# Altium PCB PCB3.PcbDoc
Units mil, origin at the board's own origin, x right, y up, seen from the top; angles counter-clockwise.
Board outline 1968.5 x 1968.5 mil, 4 copper layers (Top Layer, Internal Plane 1, Internal Plane 2, Bottom Layer), stack 18.2 mil thick; 11 components, 12 nets, 36 pads, 0 vias.
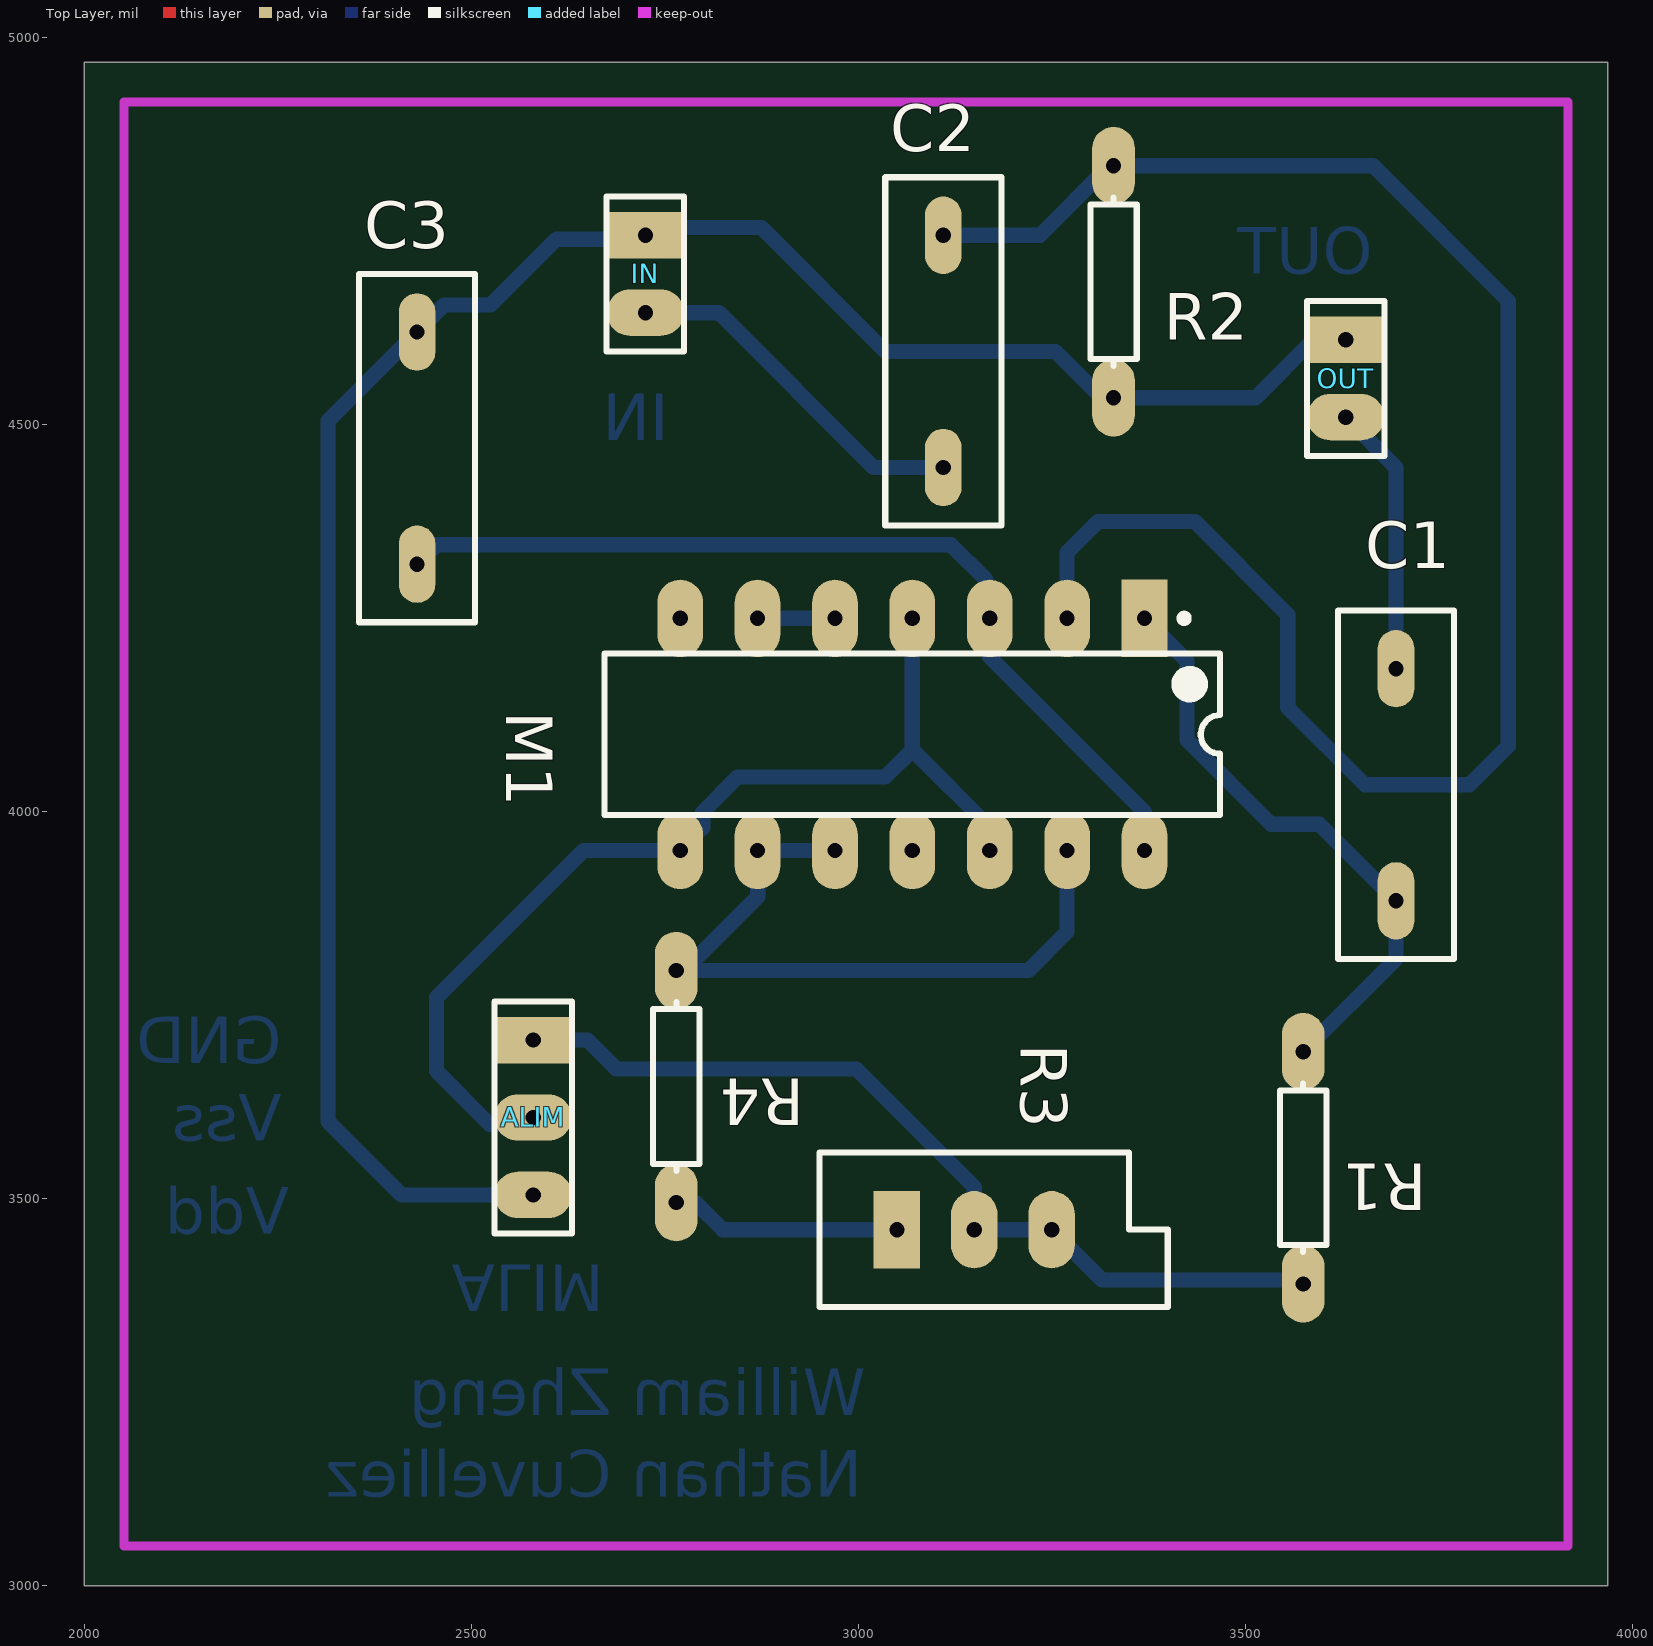
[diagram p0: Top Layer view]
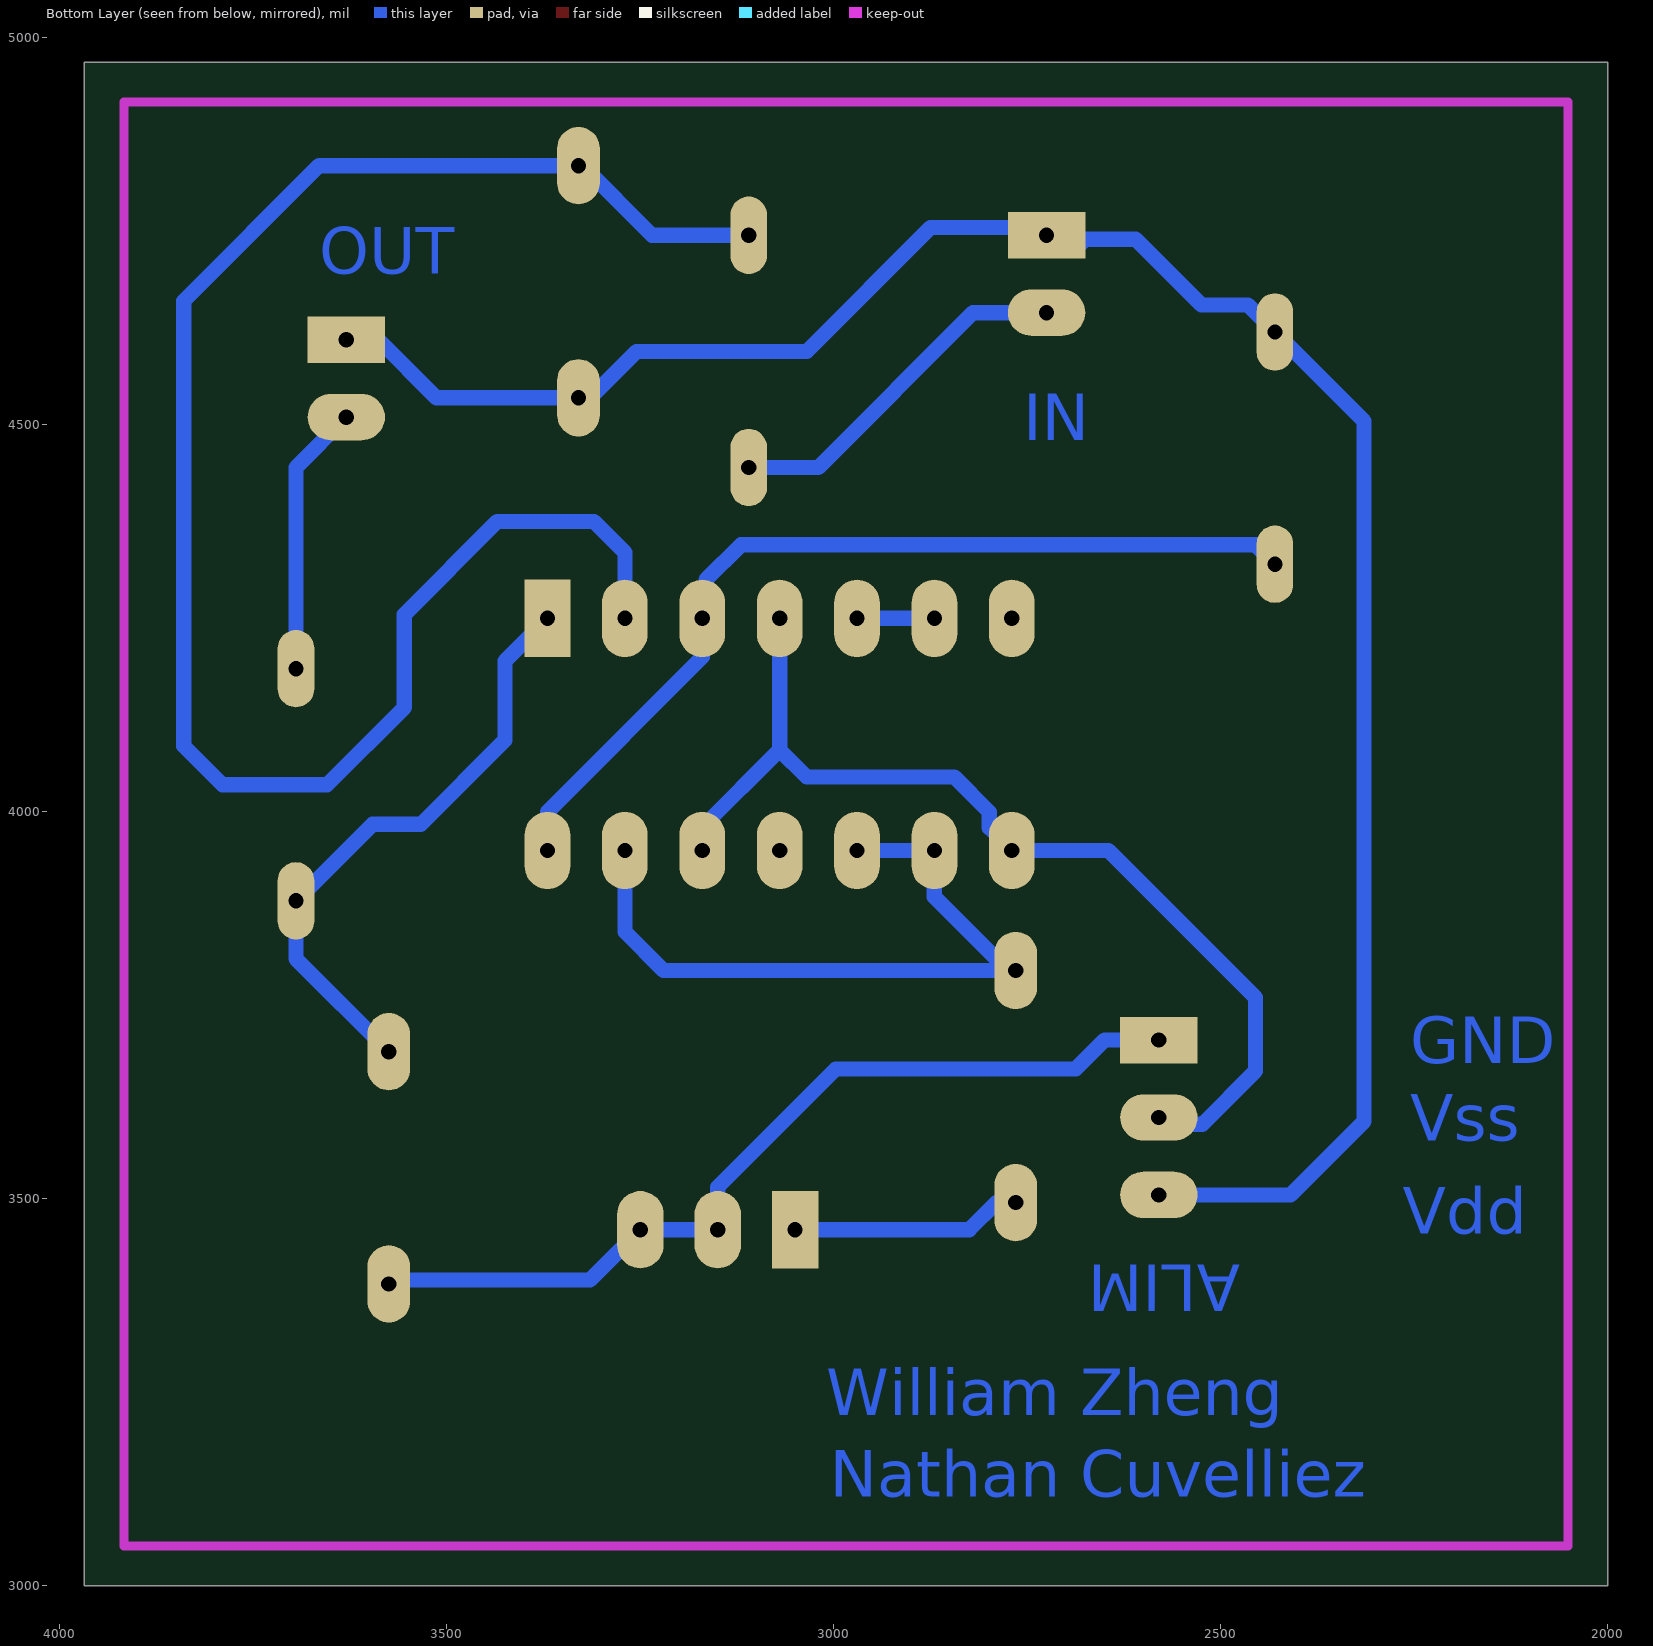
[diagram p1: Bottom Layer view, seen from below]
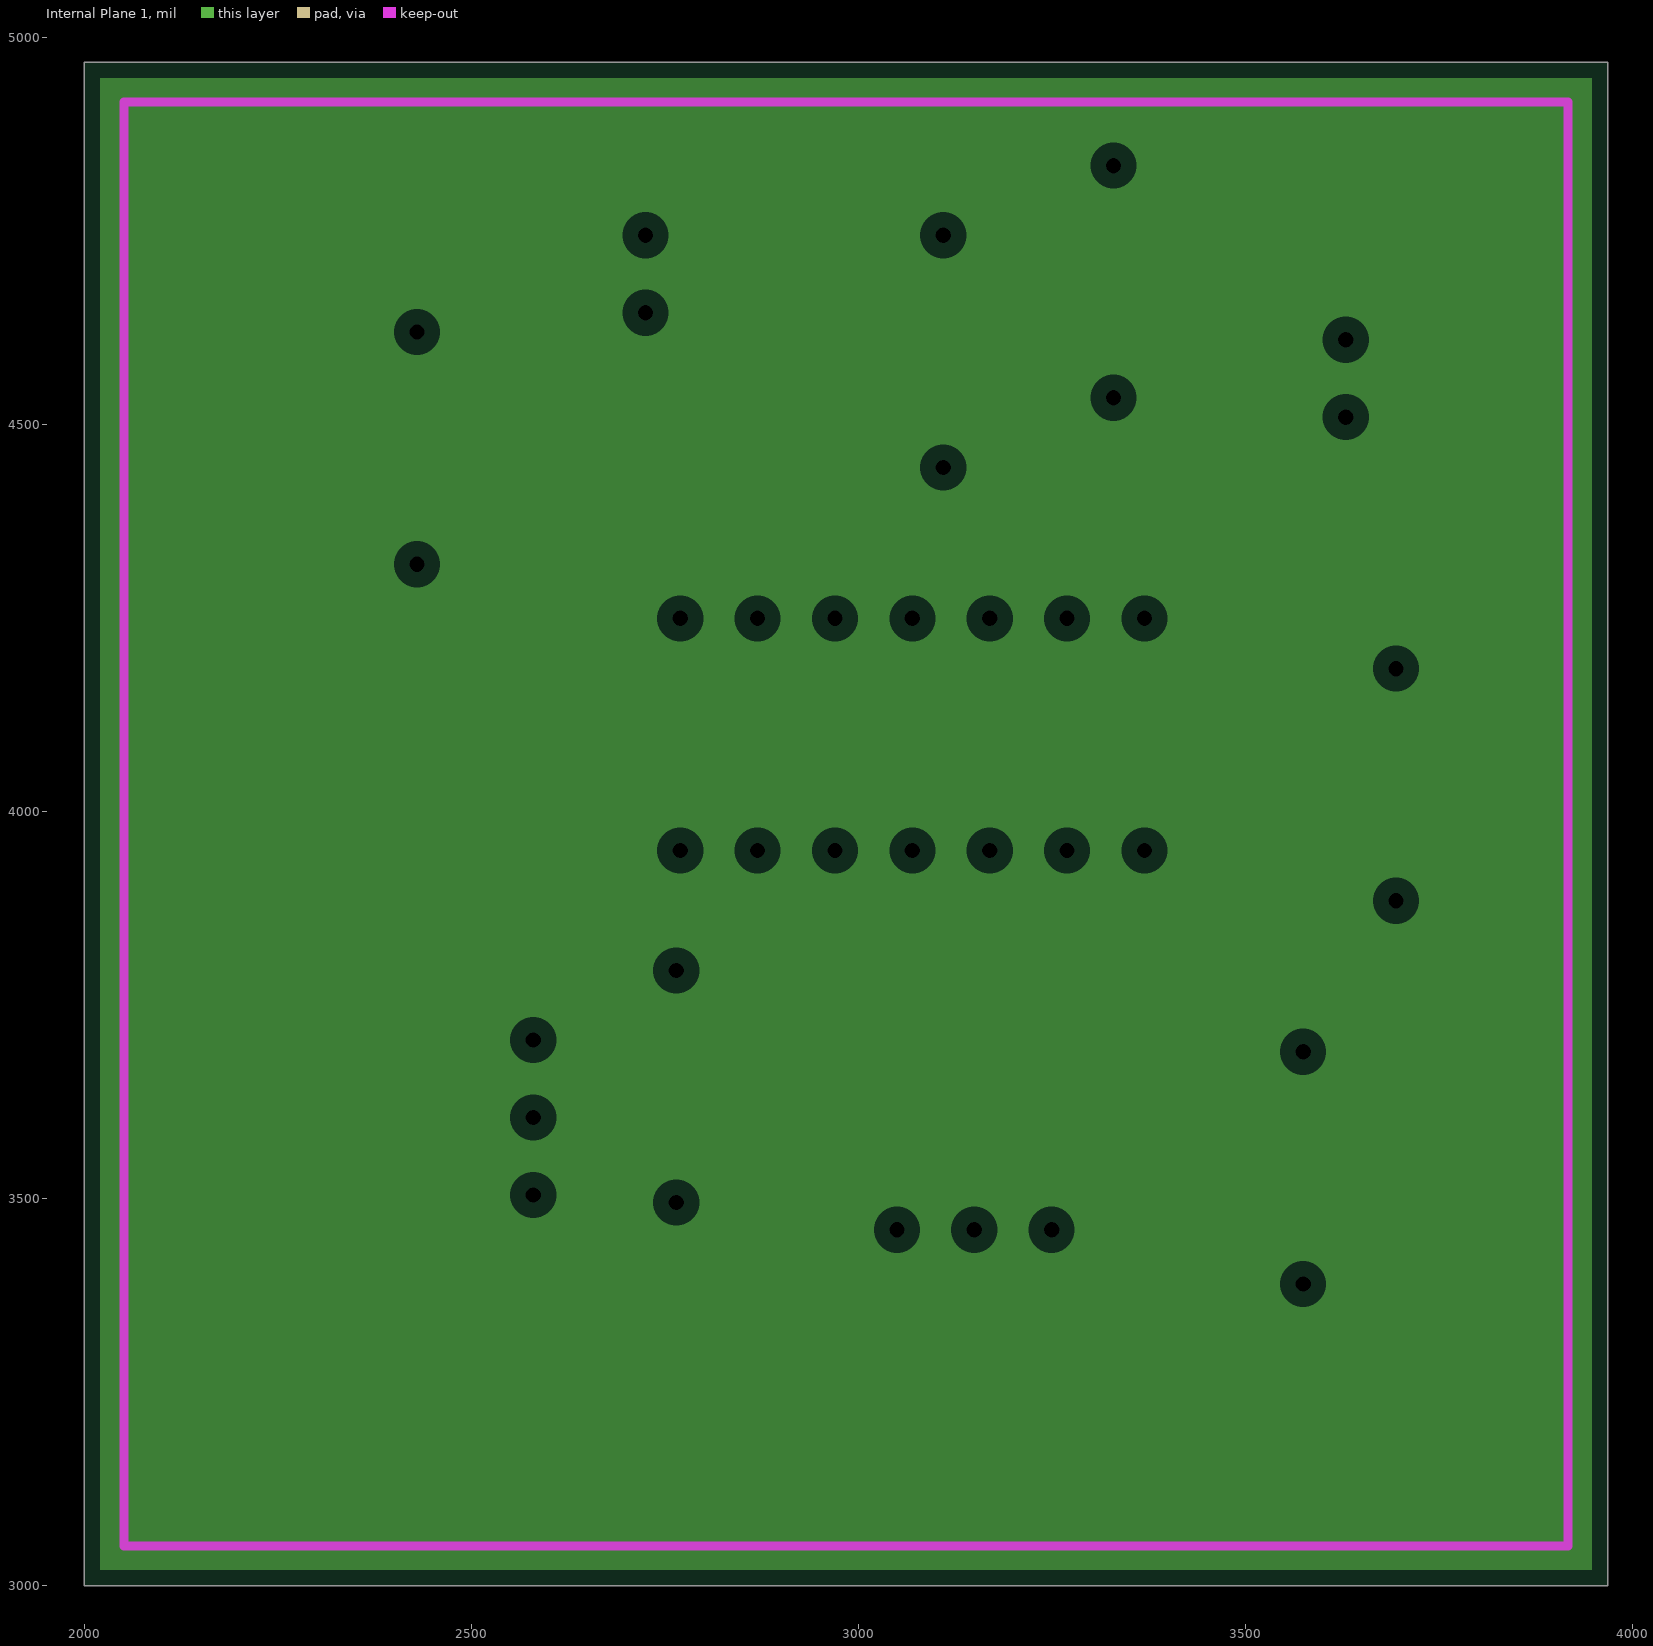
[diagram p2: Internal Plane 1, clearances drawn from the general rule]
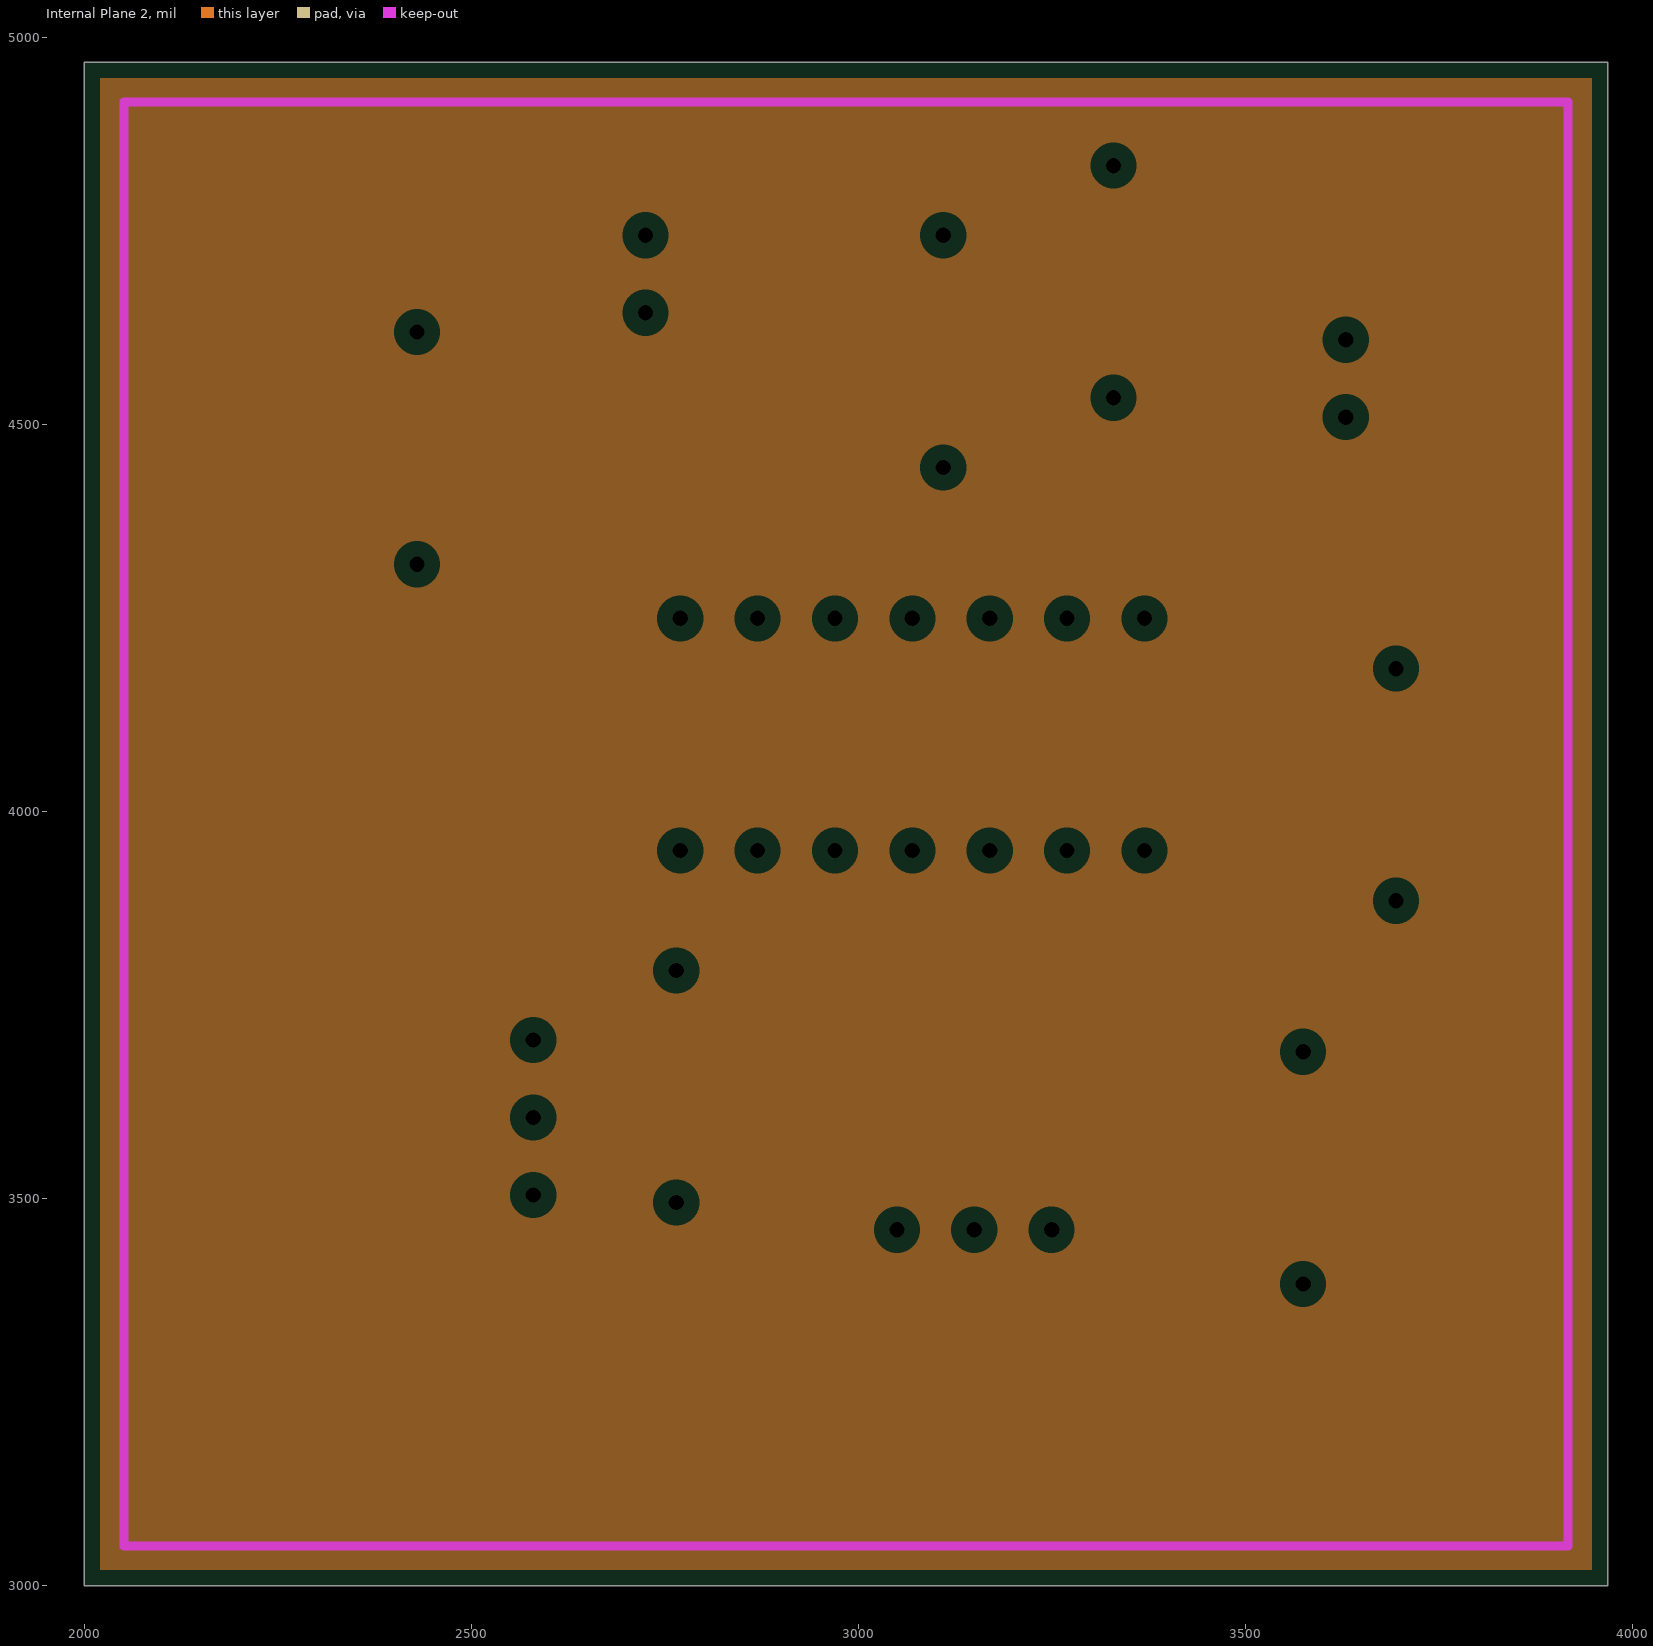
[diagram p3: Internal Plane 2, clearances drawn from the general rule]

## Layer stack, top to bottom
Top Solder: solder mask 0.4, Solder Resist, Dk 3.5
Top Layer: signal copper 1.4
Internal Plane 1: plane copper 1.4
Internal Plane 2: plane copper 1.4
Dielectric 1: dielectric 12.6, FR-4, Dk 4.8
Bottom Layer: signal copper 1.4
Bottom Solder: solder mask 0.4, Solder Resist, Dk 3.5

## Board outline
2000,3000 3968.5,3000 3968.5,4968.5 2000,4968.5

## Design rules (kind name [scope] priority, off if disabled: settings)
Clearance [All] p1: gap=31.5
PlaneClearance [All] p1: clearance=20
PlaneConnect [All] p1: planeconnectstyle=Relief reliefexpansion=20 reliefentries=4 reliefconductorwidth=10 reliefairgap=10
PolygonConnect [All] p1: connectstyle=Relief reliefconductorwidth=10 reliefentries=4 polygonreliefangle="90 Angle" airgapwidth=10
RoutingVias [All] p1: holewidth=31.5 width=62.99 viastyle="Through Hole" minholewidth=28 minwidth=50 maxholewidth=28 maxwidth=50
SolderMaskExpansion [All] p1: expansion=4
Width [All] p1: maxlimit=19.68 minlimit=19.68 preferedwidth=19.68
28 further rules are at their usual default settings.

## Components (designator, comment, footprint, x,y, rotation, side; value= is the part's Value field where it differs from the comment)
ALIM "Header 3" HDR1X3 2580,3705 r270 top
C1 "Cap" RAD-0.3 3695,4035 r90 top
C2 "Cap" RAD-0.3 3110,4595 r90 top
C3 "Cap" RAD-0.3 2430,4470 r90 top
IN "IN" HDR1X2 2725,4745 r270 top
M1 "ALD1106" DIP-14 3070,4100 r270 top
OUT "OUT" HDR1X2 3630,4610 r270 top (schematic designator Out)
R1 "Res1" AXIAL-0.3 3575,3540 r270 top
R2 "Res1" AXIAL-0.3 3330,4685 r90 top
R3 "RPot" VR5 3150,3460 r0 top
R4 "Res1" AXIAL-0.3 2765,3645 r270 top

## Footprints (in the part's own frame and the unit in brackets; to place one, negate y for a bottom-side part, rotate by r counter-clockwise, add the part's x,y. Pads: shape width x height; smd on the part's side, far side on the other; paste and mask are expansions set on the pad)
AXIAL-0.3 [mm] "Axial Device, Thru-Hole; 2 Leads; 0.3 in Pin Spacing"
  oval 2.54x1.4 hole 0.5: 1(-3.81,0) 2(3.81,0)
  silkscreen extent -2.77,-0.76 2.77,0.76
DIP-14 [mm] "DIP, 14-Pin, Row Spacing 7.62 mm, Pitch 2.54 mm"
  rect 2.54x1.5 hole 0.5: 1(-3.81,7.62)
  oval 2.54x1.5 hole 0.5: 2(-3.81,5.08) 3(-3.81,2.54) 4(-3.81,0) 5(-3.81,-2.54) 6(-3.81,-5.08) 7(-3.81,-7.62) 8(3.81,-7.62) 9(3.81,-5.08) 10(3.81,-2.54) 11(3.81,0) 12(3.81,2.54) 13(3.81,5.08) 14(3.81,7.62)
  silkscreen extent -3.93,-10.1 2.65,10.1, body extent -3.6,-10.1 3.6,10.1, height 5.08
HDR1X2 [mil] "Connector; Header; 2 Position"
  rect 60x100 hole 19.68: 1(0,0)
  oval 60x100 hole 19.68: 2(100,0)
  silkscreen extent -50,-50 150,50
HDR1X3 [mil] "Connector; Header; 3 Position"
  rect 60x100 hole 19.68: 1(0,0)
  oval 60x100 hole 19.68: 2(100,0) 3(200,0)
  silkscreen extent -50,-50 250,50
RAD-0.3 [mm] "Radial Cap, Thru-Hole; 2 Leads; 0.3 in Pin Spacing"
  oval 2.54x1.2 hole 0.5: 1(-3.81,0) 2(3.81,0)
  silkscreen extent -5.71,-1.91 5.71,1.91
VR5 [mil] "Thru-Hole; 3 Leads"
  rect 60x100 hole 19.68: 1(-100,0)
  oval 60x100 hole 19.68: 2(0,0) 3(100,0)
  silkscreen extent -200,-100 250,100

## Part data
ALIM: "Header, 3-Pin"
C1 C2 C3: "Capacitor"
IN OUT: library part "Header 2", "Header, 2-Pin"
M1: "Quad N-channel matched MOSFET array"
R1 R2 R4: "Resistor"
R3: "Potentiometer"

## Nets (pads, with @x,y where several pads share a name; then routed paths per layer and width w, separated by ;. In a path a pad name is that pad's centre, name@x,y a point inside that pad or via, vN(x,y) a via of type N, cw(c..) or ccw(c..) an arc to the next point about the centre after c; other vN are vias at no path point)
GND: ALIM.3 C3.2 IN.1 OUT.1 R2.1 | length 2663.9
  Bottom Layer w19.68: ALIM.3 2410,3505 2315,3600 2315,4505 C3.2 2465,4655 2525,4655 2610,4740 2675,4740 IN.1@2689.13,4725.87 ; IN.1@2760,4755 2875,4755 3035,4595 3255,4595 R2.1@3315,4535 ; R2.1 3513.27,4535 3588.27,4610 OUT.1
NetALIM_1: ALIM.1 R1.2 R3.2 R3.3 | length 1160.6
  Bottom Layer w19.68: ALIM.1 2650,3705 2687.5,3667.5 2997.5,3667.5 3150,3515 R3.2 R3.3 3315,3395 R1.2@3570,3395 ; R1.2@3565,3390 R1.2
NetALIM_2: ALIM.2 M1.4 M1.8 M1.12 | length 1340.8
  Bottom Layer w19.68: ALIM.2@2571.24,3596.24 2523.76,3596.24 2455,3665 2455,3760 2645,3950 M1.8 2770,3950.22 2799.13,3979.35 2799.13,3999.83 2844.31,4045 3035,4045 3070,4080 ; M1.4 3070,4080 ; M1.12 3170,3980 3070,4080
NetC1_1: C1.1 M1.1 R1.1 | length 780.9
  Bottom Layer w19.68: M1.1 3425,4195 3425,4170 3425,4092.62 3533.8,3983.82 3596.18,3983.82 C1.1 3695,3810 R1.1
NetC1_2: C1.2 OUT.2 | length 351.9
  Bottom Layer w19.68: OUT.2 3695,4445 C1.2
NetC2_1: C2.1 IN.2 | length 467.8
  Bottom Layer w19.68: IN.2 2820,4645 3020,4445 C2.1
NetC2_2: C2.2 M1.2 R2.2 | length 2313.2
  Bottom Layer w19.68: C2.2 3235,4745 R2.2@3325,4835 ; M1.2 3270,4335 3310,4375 3435,4375 3555,4255 3555,4135 3655,4035 3790,4035 3840,4085 3840,4660 3665,4835 R2.2
NetC3_1: C3.1 M1.3 M1.14 | length 1186.6
  Bottom Layer w19.68: C3.1 2455,4345 3120,4345 3165,4300 M1.3@3165,4260 ; M1.3 3170,4200 3370,4000 M1.14@3370,3950.22
NetM1_4: M1.7
NetM1_5: M1.5 M1.6 | length 101.5
  Bottom Layer w19.68: M1.6@2870,4251.51 M1.6 M1.5
NetM1_9: M1.9 M1.10 M1.13 R4.1 | length 935.1
  Bottom Layer w19.68: M1.10 M1.9 2870.06,3890.15 2775.14,3795.02 R4.1 3220,3795 3270,3845 M1.13
NetR3_1: R3.1 R4.2 | length 274.5
  Bottom Layer w19.68: R4.2@2790,3495 2825,3460 R3.1
pads on no net: M1.11

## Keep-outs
Keep-Out Layer:
  lines w11.81: 2051.18,3051.18 3917.32,3051.18 3917.32,4917.32 2051.18,4917.32 2051.18,3051.18

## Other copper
Bottom Layer:
  text "GND" at 2255,3675 h60
  text "Vss" at 2255,3575 h60
  text "Vdd" at 2265,3455 h60
  text "William Zheng" at 3010,3220 h60
  text "Nathan Cuvelliez" at 3005,3115 h60

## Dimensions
2051.18,3051.18 to 3917.32,3051.18 on Mechanical 1
2051.18,3051.18 to 2051.18,4917.32 on Mechanical 1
